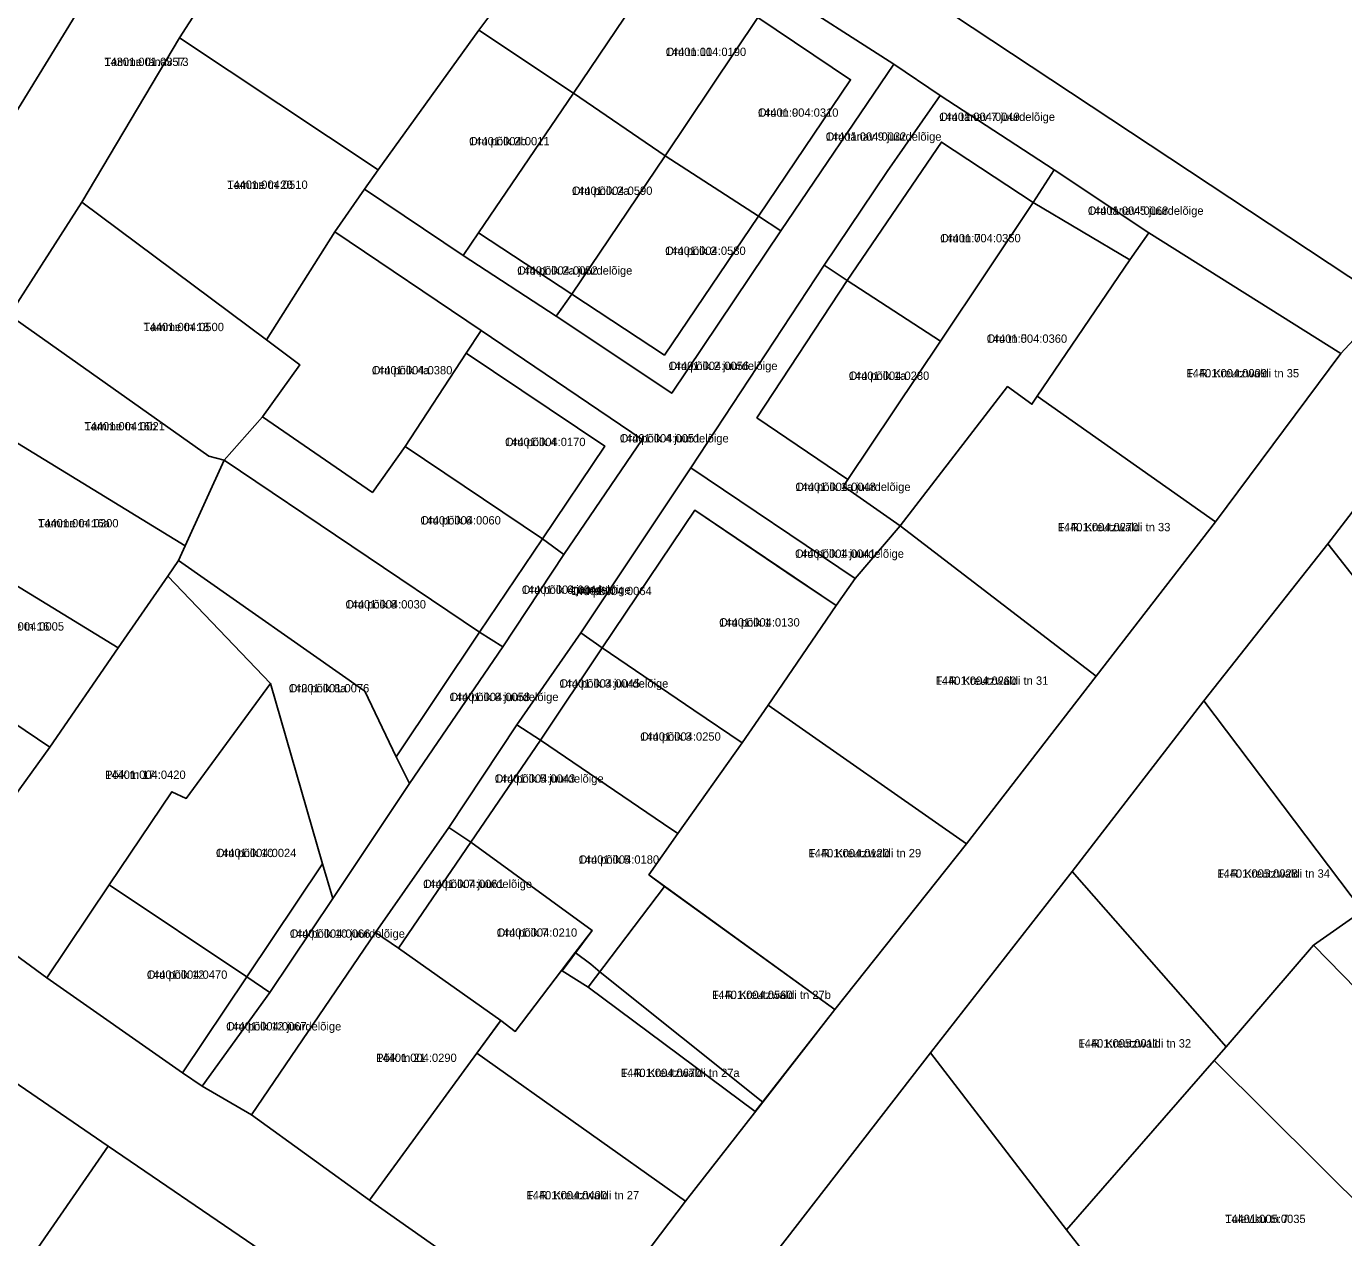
# Model space of a CAD drawing. Extents: x 640657 to 665127, y 6395726 to 6426831.
# Drawn here: x 650572.3 to 650809.6, y 6412892.7 to 6413110.9 of the extents above; entities that cross this region are included whole.
import ezdxf

# ---------------------------------------------------------------- set-up
doc = ezdxf.new("R2010")
doc.units = 0
for name, color, linetype in [('L_AADRESS', 7, 'Continuous'), ('PIIR', 7, 'Continuous'), ('TUNNUS', 7, 'Continuous')]:
    doc.layers.add(name, color=color, linetype=linetype)

msp = doc.modelspace()

# ---------------------------------------------------------------- linework, layer by layer
at = {"layer": 'PIIR'}
for points in [[(650639.81, 6413174.35), (650661.38, 6413159.66), (650687.87, 6413141.56), (650726.69, 6413115.56), (650728.32, 6413120.2), (650817.6, 6413061.15), (650809.09, 6413051.96), (650774.49, 6413073.67), (650757.49, 6413085.02), (650736.91, 6413098.43), (650728.56, 6413104.06), (650707.39, 6413117.67), (650694.6, 6413126.1), (650690.86, 6413128.47), (650674.2, 6413139.68), (650668.91, 6413143.29), (650635.45, 6413166.68)], [(650536.61, 6413122.42), (650531.75, 6413126.74), (650555.61, 6413151.56), (650587.57, 6413123.41), (650569.27, 6413093.53)], [(650619.58, 6413139.45), (650643.06, 6413123.78), (650651.55, 6413118.19), (650657.04, 6413114.5), (650653.85, 6413110.19), (650635.67, 6413085.06), (650599.89, 6413108.8)], [(650674.2, 6413139.68), (650690.86, 6413128.47), (650687.66, 6413123.7), (650670.89, 6413098.82), (650653.85, 6413110.19), (650657.04, 6413114.5)], [(650670.89, 6413098.82), (650687.66, 6413123.7), (650704.06, 6413112.49), (650687.4, 6413087.54)], [(650707.39, 6413117.67), (650728.56, 6413104.06), (650708.25, 6413074.02), (650704.19, 6413076.67), (650720.8, 6413101.26), (650704.06, 6413112.49)], [(650687.4, 6413087.54), (650704.06, 6413112.49), (650720.8, 6413101.26), (650704.19, 6413076.67)], [(650650.98, 6413069.59), (650633.24, 6413081.56), (650635.67, 6413085.06), (650653.85, 6413110.19), (650670.89, 6413098.82), (650653.78, 6413073.68)], [(650599.89, 6413108.8), (650635.67, 6413085.06), (650633.24, 6413081.56), (650627.9, 6413073.84), (650615.55, 6413054.42), (650582.29, 6413079.22)], [(650627.9, 6413073.84), (650633.24, 6413081.56), (650650.98, 6413069.59), (650667.74, 6413058.65), (650688.59, 6413044.78), (650708.25, 6413074.02), (650728.56, 6413104.06), (650736.91, 6413098.43), (650727.36, 6413084.74), (650716.02, 6413067.84), (650692, 6413031.35), (650672.18, 6413001.65), (650660.65, 6412985.07), (650648.41, 6412966.54), (650635.19, 6412947.66), (650612.9, 6412914.8), (650604.01, 6412919.95), (650616.16, 6412936.83), (650627.5, 6412953.78), (650641.36, 6412974.5), (650658.14, 6412999.13), (650669.15, 6413015.75), (650683.26, 6413036.48), (650654.24, 6413056.11)], [(650653.78, 6413073.68), (650670.89, 6413098.82), (650687.4, 6413087.54), (650670.59, 6413062.66)], [(650736.91, 6413098.43), (650757.49, 6413085.02), (650753.68, 6413079.15), (650737.14, 6413090.04), (650720.19, 6413065.09), (650716.02, 6413067.84), (650727.36, 6413084.74)], [(650737.14, 6413090.04), (650753.68, 6413079.15), (650736.99, 6413054.19), (650720.19, 6413065.09)], [(650670.59, 6413062.66), (650687.4, 6413087.54), (650704.19, 6413076.67), (650687.25, 6413051.68)], [(650757.49, 6413085.02), (650774.49, 6413073.67), (650771.12, 6413068.84), (650753.68, 6413079.15)], [(650582.29, 6413079.22), (650615.55, 6413054.42), (650621.57, 6413049.93), (650614.85, 6413040.56), (650607.93, 6413032.74), (650605.2, 6413033.45), (650569.28, 6413058.87)], [(650729.7, 6413020.92), (650719.49, 6413028.07), (650720.32, 6413029.28), (650736.99, 6413054.19), (650753.68, 6413079.15), (650771.12, 6413068.84), (650754.38, 6413044.25), (650753.44, 6413042.82), (650749.07, 6413046)], [(650670.59, 6413062.66), (650687.25, 6413051.68), (650704.19, 6413076.67), (650708.25, 6413074.02), (650688.59, 6413044.78), (650667.74, 6413058.65)], [(650627.9, 6413073.84), (650654.24, 6413056.11), (650651.55, 6413051.99), (650640.53, 6413035.2), (650634.67, 6413026.92), (650614.85, 6413040.56), (650621.57, 6413049.93), (650615.56, 6413054.43)], [(650650.98, 6413069.59), (650653.78, 6413073.68), (650670.59, 6413062.66), (650667.74, 6413058.65)], [(650786.55, 6413021.63), (650754.38, 6413044.25), (650771.12, 6413068.84), (650774.49, 6413073.67), (650809.09, 6413051.96)], [(650716.02, 6413067.84), (650720.19, 6413065.09), (650703.93, 6413040.38), (650720.32, 6413029.28), (650719.49, 6413028.07), (650729.7, 6413020.92), (650721.63, 6413011.44), (650692, 6413031.35)], [(650720.19, 6413065.09), (650736.99, 6413054.19), (650720.32, 6413029.28), (650703.93, 6413040.38)], [(650559.96, 6413042.34), (650569.28, 6413058.87), (650605.2, 6413033.45), (650607.93, 6413032.74), (650600.92, 6413017.32)], [(650651.55, 6413051.99), (650654.24, 6413056.11), (650683.26, 6413036.48), (650669.15, 6413015.75), (650665.28, 6413018.56), (650676.51, 6413035.27)], [(650651.55, 6413051.99), (650676.51, 6413035.27), (650665.28, 6413018.56), (650640.53, 6413035.2)], [(650729.7, 6413020.92), (650749.07, 6413046), (650753.44, 6413042.82), (650754.38, 6413044.25), (650786.55, 6413021.63), (650765.03, 6412993.85)], [(650559.96, 6413042.34), (650600.92, 6413017.32), (650599.7, 6413014.64), (650597.83, 6413011.87), (650588.87, 6412998.92), (650549.45, 6413023.01)], [(650614.85, 6413040.56), (650634.67, 6413026.92), (650640.53, 6413035.2), (650665.28, 6413018.56), (650653.97, 6413001.73), (650607.93, 6413032.74)], [(650806.76, 6413017.69), (650817.7, 6413031.91), (650822.51, 6413038.14), (650823.57, 6413038.25), (650829.61, 6413033.56), (650834.03, 6413029.42), (650857.25, 6413001.69), (650858.72, 6412999.99), (650839.66, 6412980.52), (650838.08, 6412978.9), (650819.54, 6413001.38)], [(650599.7, 6413014.64), (650600.92, 6413017.32), (650607.93, 6413032.74), (650653.97, 6413001.73), (650638.96, 6412979.31), (650633.28, 6412991.15)], [(650692, 6413031.35), (650721.63, 6413011.44), (650718.2, 6413006.54), (650692.73, 6413023.72), (650676.04, 6412998.94), (650672.18, 6413001.65)], [(650538.74, 6413006.57), (650549.45, 6413023.01), (650588.87, 6412998.92), (650576.52, 6412981.06)], [(650692.73, 6413023.72), (650709.32, 6413012.53), (650718.2, 6413006.54), (650705.93, 6412988.63), (650701.26, 6412981.82), (650692.57, 6412987.7), (650676.04, 6412998.94)], [(650705.93, 6412988.63), (650718.2, 6413006.54), (650721.63, 6413011.44), (650729.7, 6413020.92), (650765.03, 6412993.85), (650741.65, 6412963.62)], [(650653.97, 6413001.73), (650665.28, 6413018.56), (650669.15, 6413015.75), (650658.14, 6412999.13)], [(650806.76, 6413017.69), (650819.54, 6413001.38), (650838.08, 6412978.9), (650821.71, 6412962.79), (650813.02, 6412951.56), (650784.43, 6412989.36)], [(650597.83, 6413011.87), (650599.7, 6413014.64), (650633.28, 6412991.15), (650638.96, 6412979.31), (650641.36, 6412974.5), (650627.5, 6412953.78), (650625.69, 6412960.03), (650616.29, 6412992.52)], [(650575.99, 6412939.48), (650556.73, 6412953.59), (650576.52, 6412981.06), (650588.87, 6412998.92), (650597.83, 6413011.87), (650616.29, 6412992.52), (650601.13, 6412971.82), (650598.5, 6412973.02), (650587.24, 6412956.25)], [(650538.74, 6413006.57), (650576.52, 6412981.06), (650556.73, 6412953.59), (650521.58, 6412978.11)], [(650638.96, 6412979.31), (650653.97, 6413001.73), (650658.14, 6412999.13), (650641.36, 6412974.5)], [(650660.65, 6412985.07), (650672.18, 6413001.65), (650676.04, 6412998.94), (650664.96, 6412982.32)], [(650676.04, 6412998.94), (650692.57, 6412987.7), (650701.26, 6412981.82), (650689.68, 6412965.48), (650687.06, 6412967.26), (650664.96, 6412982.32)], [(650612.04, 6412939.65), (650587.24, 6412956.25), (650598.5, 6412973.02), (650601.13, 6412971.82), (650616.29, 6412992.52), (650625.69, 6412960.03)], [(650760.68, 6412958.63), (650784.43, 6412989.36), (650813.02, 6412951.56), (650804.18, 6412945.36), (650788.46, 6412927.08)], [(650717.93, 6412933.8), (650684.46, 6412958.07), (650689.68, 6412965.48), (650701.26, 6412981.82), (650705.93, 6412988.63), (650741.65, 6412963.62)], [(650648.41, 6412966.54), (650660.65, 6412985.07), (650664.96, 6412982.32), (650652.4, 6412963.95)], [(650664.96, 6412982.32), (650687.06, 6412967.26), (650689.68, 6412965.48), (650684.46, 6412958.07), (650687.26, 6412955.94), (650673.51, 6412937.79), (650668.86, 6412940.74), (650674.23, 6412948.04), (650652.4, 6412963.95)], [(650648.41, 6412966.54), (650652.4, 6412963.95), (650639.33, 6412944.86), (650635.19, 6412947.66)], [(650652.4, 6412963.95), (650674.23, 6412948.04), (650671.18, 6412944.03), (650660.38, 6412929.85), (650657.79, 6412931.83), (650639.33, 6412944.86)], [(650843.09, 6412905.57), (650804.18, 6412945.36), (650813.02, 6412951.56), (650821.71, 6412962.79), (650862, 6412923.4)], [(650612.04, 6412939.65), (650625.69, 6412960.03), (650627.5, 6412953.78), (650616.16, 6412936.83)], [(650760.68, 6412958.63), (650788.46, 6412927.08), (650786.31, 6412924.61), (650759.7, 6412894.12), (650735.21, 6412925.98)], [(650587.24, 6412956.25), (650612.04, 6412939.65), (650600.47, 6412922.38), (650575.99, 6412939.48)], [(650687.26, 6412955.94), (650717.93, 6412933.8), (650703.62, 6412915.41), (650673.51, 6412937.79)], [(650612.9, 6412914.8), (650635.19, 6412947.66), (650639.33, 6412944.86), (650657.79, 6412931.83), (650653.47, 6412925.91), (650634.13, 6412899.46)], [(650653.47, 6412925.91), (650657.56, 6412931.51), (650657.79, 6412931.83), (650660.38, 6412929.85), (650671.18, 6412944.03), (650673.98, 6412941.95), (650675.69, 6412940.54), (650704.96, 6412917.1), (650691.08, 6412899.24)], [(650786.31, 6412924.61), (650788.46, 6412927.08), (650804.18, 6412945.36), (650843.09, 6412905.57), (650824.08, 6412887.05)], [(650612.04, 6412939.65), (650616.16, 6412936.83), (650604.01, 6412919.95), (650600.47, 6412922.38)], [(650587.03, 6412909.19), (650570.41, 6412885.11), (650528.27, 6412908.65), (650547.67, 6412936.14)], [(650653.47, 6412925.91), (650691.08, 6412899.24), (650671.35, 6412873.26), (650634.13, 6412899.46)], [(650735.21, 6412925.98), (650759.7, 6412894.12), (650772.63, 6412877.46), (650761.52, 6412867.85), (650741.97, 6412851.94), (650720.2, 6412876.12), (650707.5, 6412890.28)], [(650759.7, 6412894.12), (650786.31, 6412924.61), (650824.08, 6412887.05), (650802.47, 6412866.04), (650783.09, 6412886.6), (650780.41, 6412884.25), (650772.63, 6412877.46)], [(650587.03, 6412909.19), (650613.3, 6412891.26), (650596.19, 6412868.66), (650582.65, 6412850.8), (650565.69, 6412829.54), (650562.63, 6412831.16), (650544.44, 6412845.81), (650570.41, 6412885.11)]]:
    msp.add_lwpolyline(points, close=True, dxfattribs=at)
for points in [[(650619.58, 6413139.45), (650599.89, 6413108.8), (650582.29, 6413079.22), (650569.28, 6413058.87), (650559.96, 6413042.34), (650549.45, 6413023.01), (650538.74, 6413006.57), (650521.58, 6412978.11), (650506.59, 6412989.76), (650524.64, 6413019.61), (650536.83, 6413039.67), (650548.62, 6413059.33), (650569.27, 6413093.53), (650587.57, 6413123.41)], [(650817.6, 6413061.15), (650728.32, 6413120.2)], [(650401.68, 6412620.02), (650443.31, 6412635.66), (650502.99, 6412658.87), (650531.76, 6412695.05), (650559.55, 6412729.99), (650584.65, 6412761.55), (650611.45, 6412796.26), (650628.07, 6412817.98), (650642.14, 6412836.53), (650659.43, 6412858.77), (650671.35, 6412873.26), (650691.08, 6412899.24), (650704.96, 6412917.1), (650717.93, 6412933.8), (650741.65, 6412963.62), (650765.03, 6412993.85), (650786.55, 6413021.63), (650809.09, 6413051.96), (650817.6, 6413061.15)], [(650817.7, 6413031.91), (650806.76, 6413017.69), (650784.43, 6412989.36), (650760.68, 6412958.63), (650735.21, 6412925.98), (650707.5, 6412890.28), (650682.06, 6412857.34), (650670.16, 6412841.93), (650650.26, 6412816.25), (650622.9, 6412780.36), (650600.95, 6412752.04), (650584, 6412729.6), (650523.13, 6412650.87), (650462.26, 6412625.96)], [(650556.73, 6412953.59), (650575.99, 6412939.48), (650600.47, 6412922.38), (650604.01, 6412919.95), (650612.9, 6412914.8), (650634.13, 6412899.46), (650671.35, 6412873.26), (650659.43, 6412858.77), (650638.35, 6412874), (650613.3, 6412891.26), (650587.03, 6412909.19), (650547.67, 6412936.14)]]:
    msp.add_lwpolyline(points, dxfattribs=at)

# ---------------------------------------------------------------- texts
at = {"layer": 'L_AADRESS'}
for s, p in [('Tamme tänav T3', (650586.36, 6413103.74)), ('Oru tn 11', (650687.48, 6413105.54)), ('Oru tn 9', (650704.1, 6413094.6)), ('Oru tänav 7 juurdelõige', (650736.76, 6413093.84)), ('Oru põik 2b', (650652.07, 6413089.45)), ('Oru tänav 9 juurdelõige', (650716.31, 6413090.28)), ('Tamme tn 20', (650608.49, 6413081.61)), ('Oru põik 2a', (650670.59, 6413080.52)), ('Oru tänav 5 juurdelõige', (650763.52, 6413076.93)), ('Oru tn 7', (650736.93, 6413071.98)), ('Oru põik 2', (650687.39, 6413069.71)), ('Oru põik 2a juurdelõige', (650660.74, 6413066.16)), ('Tamme tn 18', (650593.41, 6413055.98)), ('Oru tn 5', (650745.3, 6413053.88)), ('Oru põik 2 juurdelõige', (650688, 6413048.98)), ('Oru põik 4a', (650634.55, 6413048.19)), ('Oru põik 1a', (650720.46, 6413047.2)), ('F. R. Kreutzwaldi tn 35', (650781.29, 6413047.65)), ('Tamme tn 16b', (650582.77, 6413038.1)), ('Oru põik 4', (650658.54, 6413035.27)), ('Oru põik 4 juurdelõige', (650679.21, 6413035.93)), ('Oru põik 1a juurdelõige', (650710.85, 6413027.19)), ('Tamme tn 16a', (650574.42, 6413020.63)), ('Oru põik 6', (650643.29, 6413021.15)), ('F. R. Kreutzwaldi tn 33', (650758.11, 6413019.93)), ('Oru põik 1 juurdelõige', (650710.78, 6413015.15)), ('Oru põik 6 juurdelõige', (650661.56, 6413008.66)), ('Oru põik', (650670.46, 6413008.43)), ('Oru põik 8', (650629.8, 6413006.02)), ('Tamme tn 16', (650564.61, 6413002.04)), ('Oru põik 1', (650697.12, 6413002.77)), ('F. R. Kreutzwaldi tn 31', (650736.12, 6412992.27)), ('Oru põik 8a', (650619.59, 6412990.91)), ('Oru põik 3 juurdelõige', (650668.34, 6412991.77)), ('Oru põik 8 juurdelõige', (650648.55, 6412989.34)), ('Oru põik 3', (650682.9, 6412982.21)), ('Põik tn 17', (650586.51, 6412975.33)), ('Oru põik 5 juurdelõige', (650656.68, 6412974.64)), ('Oru põik 10', (650606.46, 6412961.24)), ('F. R. Kreutzwaldi tn 29', (650713.21, 6412961.21)), ('Oru põik 5', (650671.8, 6412960.05)), ('F. R. Kreutzwaldi tn 34', (650786.85, 6412957.53)), ('Oru põik 7 juurdelõige', (650643.79, 6412955.67)), ('Oru põik 7', (650657.04, 6412946.9)), ('Oru põik 10 juurdelõige', (650619.77, 6412946.71)), ('Oru põik 12', (650594.02, 6412939.32)), ('F. R. Kreutzwaldi tn 27b', (650695.84, 6412935.68)), ('Oru põik 12 juurdelõige', (650608.31, 6412930.01)), ('F. R. Kreutzwaldi tn 32', (650761.84, 6412926.94)), ('Põik tn 21', (650635.34, 6412924.34)), ('F. R. Kreutzwaldi tn 27a', (650679.4, 6412921.63)), ('F. R. Kreutzwaldi tn 27', (650662.41, 6412899.59)), ('Tuleviku tn 7', (650788.26, 6412895.32))]:
    msp.add_text(s, height=1.5, dxfattribs=at).set_placement(p)
at = {"layer": 'TUNNUS'}
for s, p in [('14301:001:0357', (650586.36, 6413103.74)), ('14401:004:0190', (650687.48, 6413105.54)), ('14401:004:0310', (650704.1, 6413094.6)), ('14401:004:0049', (650736.76, 6413093.84)), ('14401:004:0011', (650652.07, 6413089.45)), ('14401:004:0032', (650716.31, 6413090.28)), ('14401:004:0510', (650608.49, 6413081.61)), ('14401:004:0590', (650670.59, 6413080.52)), ('14401:004:0068', (650763.52, 6413076.93)), ('14401:004:0350', (650736.93, 6413071.98)), ('14401:004:0580', (650687.39, 6413069.71)), ('14401:004:0052', (650660.74, 6413066.16)), ('14401:004:0500', (650593.41, 6413055.98)), ('14401:004:0360', (650745.3, 6413053.88)), ('14401:004:0056', (650688, 6413048.98)), ('14401:004:0380', (650634.55, 6413048.19)), ('14401:004:0280', (650720.46, 6413047.2)), ('14401:004:0009', (650781.29, 6413047.65)), ('14401:004:0021', (650582.77, 6413038.1)), ('14401:004:0170', (650658.54, 6413035.27)), ('14401:004:0051', (650679.21, 6413035.93)), ('14401:004:0048', (650710.85, 6413027.19)), ('14401:004:0300', (650574.42, 6413020.63)), ('14401:004:0060', (650643.29, 6413021.15)), ('14401:004:0270', (650758.11, 6413019.93)), ('14401:004:0041', (650710.78, 6413015.15)), ('14401:004:0044', (650661.56, 6413008.66)), ('14401:004:0064', (650670.46, 6413008.43)), ('14401:004:0030', (650629.8, 6413006.02)), ('14401:004:0005', (650564.61, 6413002.04)), ('14401:004:0130', (650697.12, 6413002.77)), ('14401:004:0260', (650736.12, 6412992.27)), ('14201:001:0076', (650619.59, 6412990.91)), ('14401:004:0045', (650668.34, 6412991.77)), ('14401:004:0058', (650648.55, 6412989.34)), ('14401:004:0250', (650682.9, 6412982.21)), ('14401:004:0420', (650586.51, 6412975.33)), ('14401:004:0043', (650656.68, 6412974.64)), ('14401:004:0024', (650606.46, 6412961.24)), ('14401:004:0120', (650713.21, 6412961.21)), ('14401:004:0180', (650671.8, 6412960.05)), ('14401:005:0028', (650786.85, 6412957.53)), ('14401:004:0061', (650643.79, 6412955.67)), ('14401:004:0066', (650619.77, 6412946.71)), ('14401:004:0210', (650657.04, 6412946.9)), ('14401:004:0470', (650594.02, 6412939.32)), ('14401:004:0560', (650695.84, 6412935.68)), ('14401:004:0067', (650608.31, 6412930.01)), ('14401:005:0011', (650761.84, 6412926.94)), ('14401:004:0290', (650635.34, 6412924.34)), ('14401:004:0670', (650679.4, 6412921.63)), ('14401:004:0400', (650662.41, 6412899.59)), ('14401:005:0035', (650788.26, 6412895.32))]:
    msp.add_text(s, height=1.5, dxfattribs=at).set_placement(p)

doc.saveas('drawing.dxf')
